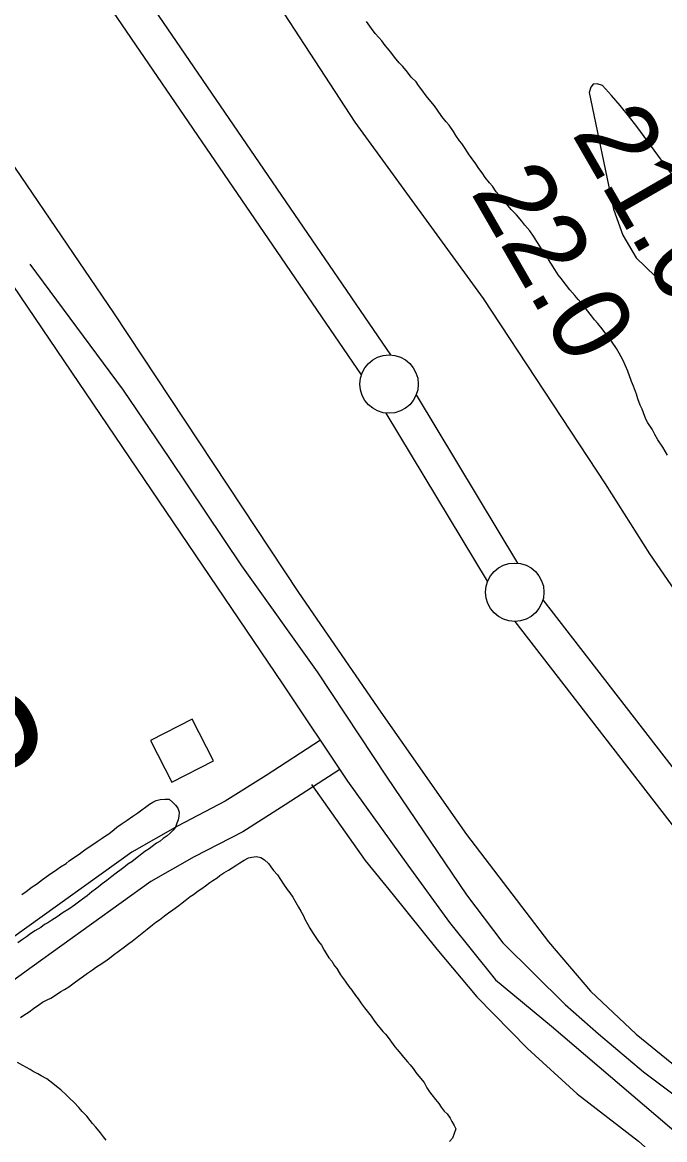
# Model space of a CAD drawing. Extents: x 3297753 to 3335611, y 652252 to 677623.
# Drawn here: x 3308297 to 3308846, y 669630 to 670586 of the extents above; entities that cross this region are included whole.
import ezdxf

# ---------------------------------------------------------------- set-up
doc = ezdxf.new("R2010")
doc.units = 0
for name, color, linetype in [('V-BLDG-OTLN', 7, 'Continuous'), ('V-LEVE-TOET', 7, 'Continuous'), ('V-RIVR-EDGE', 7, 'Continuous'), ('V-RIVR-RANG', 7, 'Continuous'), ('V-ROAD-CNTR', 7, 'Continuous'), ('V-SURV-IDEN', 7, 'Continuous'), ('V-SURV-LINE', 7, 'Continuous'), ('V-TOPO-MINR', 7, 'Continuous'), ('V-TOPO-SHOR', 7, 'Continuous')]:
    doc.layers.add(name, color=color, linetype=linetype)

msp = doc.modelspace()

# ---------------------------------------------------------------- linework, layer by layer
at = {"layer": 'V-BLDG-OTLN'}
msp.add_lwpolyline([(3308460.48, 669953.81), (3308442.28, 669989.42), (3308406.66, 669971.22), (3308424.87, 669935.6)], close=True, dxfattribs=at)
at = {"layer": 'V-LEVE-TOET'}
for points in [[(3308133.21, 670684.14), (3308250.51, 670519.66), (3308374.97, 670337.24), (3308533.16, 670097.88), (3308603.72, 669995.31), (3308676.85, 669890.86), (3308746.98, 669798.88), (3308783.09, 669756.81), (3308822.07, 669719.91), (3308908.96, 669649.25), (3309055.84, 669538.15), (3309202.86, 669430.58), (3309382.89, 669290.76), (3309531.09, 669190.18), (3309660.89, 669092.14), (3309690.67, 669067.09), (3309712.65, 669045.01), (3309817.76, 668967.41), (3309910.78, 668895.61), (3309933.41, 668877.39), (3310042.12, 668792.22), (3310236.32, 668633.29)], [(3308495.25, 670632.62), (3308581.29, 670500.31), (3308691.23, 670349.36), (3308795.55, 670190.72), (3308833.56, 670130.94), (3308923.2, 670000.24), (3308977.77, 669936.24), (3309079.06, 669851.75), (3309174.42, 669772.8), (3309318.58, 669660.06), (3309436.74, 669578.38), (3309522.36, 669519.23), (3309584.85, 669454.89), (3309681.74, 669370.59), (3309778.17, 669296), (3309850.52, 669235.65), (3309961.42, 669148.99), (3309983.33, 669131.68), (3310092.83, 669047.36), (3310290.15, 668899.76), (3310517.11, 668723.58)]]:
    msp.add_lwpolyline(points, dxfattribs=at)
at = {"layer": 'V-RIVR-EDGE'}
msp.add_spline([(3307850.62, 675821), (3307850.75, 675819.26), (3307852.36, 675798.53), (3307852.34, 675791.07), (3307856.9, 675791.47), (3307860.2, 675784), (3307858.08, 675766.6), (3307858.03, 675745.87), (3307859.68, 675743.8), (3307863.41, 675742.96), (3307863.4, 675739.64), (3307862.94, 675720.99), (3307866.19, 675694.04), (3307864.47, 675668.35), (3307864.85, 675653.43), (3307866.04, 675632.29), (3307865.98, 675608.25), (3307860.93, 675578), (3307855.03, 675536.15), (3307852.01, 675490.98), (3307848.61, 675457.42), (3307845.62, 675420.95), (3307843.09, 675401.89), (3307841.81, 675387.8), (3307842.17, 675364.59), (3307841.69, 675337.23), (3307844.13, 675320.65), (3307845.74, 675299.92), (3307848.96, 675263.02), (3307851.37, 675230.27), (3307851.72, 675204.99), (3307854.14, 675179.28), (3307856.98, 675153.99), (3307856.53, 675138.24), (3307855.69, 675135.76), (3307856.07, 675118.35), (3307855.63, 675111.72), (3307854.35, 675095.97), (3307852.65, 675077.74), (3307852.18, 675054.11), (3307855.44, 675031.72), (3307862.38, 674991.5), (3307864.8, 674962.48), (3307868.44, 674926), (3307870.05, 674906.1), (3307872.46, 674875.01), (3307874.08, 674859.25), (3307876.52, 674843.5), (3307878.94, 674816.13), (3307882.53, 674757.68), (3307886.15, 674712.5), (3307885.71, 674704.21), (3307884.45, 674697.99), (3307884.44, 674691.78), (3307887.31, 674680.16), (3307887.28, 674668.97), (3307887.26, 674658.2), (3307885.58, 674651.15), (3307881.01, 674644.12), (3307881, 674639.97), (3307886.35, 674626.28), (3307890.03, 674605.55), (3307895.77, 674578.59), (3307899.43, 674550.81), (3307909.27, 674510.58), (3307914.59, 674481.97), (3307918.25, 674453.78), (3307918.22, 674440.51), (3307919.86, 674433.88), (3307927.3, 674423.08), (3307927.28, 674417.7), (3307927.25, 674404.02), (3307928.48, 674400.28), (3307931.78, 674393.23), (3307935.06, 674376.64), (3307944.54, 674357.55), (3307954.85, 674337.22), (3307963.92, 674316.06), (3307975.42, 674271.68), (3307986.49, 674225.23), (3308000.06, 674178.77), (3308007.44, 674148.91), (3308015.22, 674108.27), (3308020.53, 674078.42), (3308024.25, 674072.19), (3308025.04, 674059.34), (3308025.41, 674039.44), (3308027.79, 673997.16), (3308030.63, 673971.46), (3308027.69, 673955.3), (3308027.24, 673943.28), (3308027.64, 673935.82), (3308029.69, 673925.45), (3308035.46, 673911.76), (3308035.42, 673899.32), (3308034.12, 673873.21), (3308036.13, 673851.24), (3308038.54, 673818.91), (3308040.98, 673799), (3308046.76, 673788.21), (3308050.46, 673778.26), (3308048.79, 673772.46), (3308048.76, 673761.27), (3308053.68, 673740.53), (3308060.66, 673711.09), (3308069.7, 673678.73), (3308069.66, 673665.06), (3308067.15, 673653.46), (3308067.55, 673650.14), (3308072.94, 673649.3), (3308077.91, 673648.87), (3308079.98, 673646.38), (3308086.52, 673608.64), (3308091.84, 673582.1), (3308104.58, 673536.48), (3308114.83, 673495), (3308121.38, 673461), (3308123.83, 673446.07), (3308127.95, 673436.12), (3308140.31, 673406.24), (3308148.95, 673377.21), (3308153.04, 673357.72), (3308158.34, 673321.23), (3308169, 673273.12), (3308189.1, 673188.1), (3308196.88, 673150.37), (3308207.96, 673103.92), (3308212.04, 673079.45), (3308214.06, 673059.97), (3308216.51, 673045.04), (3308218.98, 673035.91), (3308226, 673025.53), (3308228.46, 673015.99), (3308228.43, 673002.32), (3308230.49, 672996.92), (3308235.04, 672992.77), (3308235.02, 672984.48), (3308237.47, 672972.87), (3308241.99, 672953.37), (3308247.32, 672933.05), (3308253.9, 672910.65), (3308257.61, 672901.53), (3308263.8, 672890.32), (3308276.17, 672865), (3308277.39, 672856.3), (3308278.62, 672850.08), (3308283.16, 672844.26), (3308286.05, 672839.7), (3308286.04, 672832.24), (3308285.59, 672818.97), (3308288.47, 672812.33), (3308293.83, 672800.3), (3308303.72, 672777.89), (3308309.9, 672762.54), (3308316.07, 672743.05), (3308316.44, 672725.64), (3308318.1, 672723.15), (3308323.06, 672717.33), (3308327.59, 672706.13), (3308331.69, 672690.37), (3308330.84, 672679.6), (3308330.4, 672672.14), (3308332.46, 672667.16), (3308337.42, 672658.44), (3308343.59, 672642.67), (3308347.7, 672625.26), (3308355.91, 672595.39), (3308355.89, 672584.62), (3308357.53, 672579.64), (3308362.07, 672570.92), (3308366.61, 672563.45), (3308376.07, 672534), (3308399.56, 672478.4), (3308411.51, 672452.67), (3308418.52, 672435.25), (3308421.79, 672418.66), (3308423.01, 672409.95), (3308425.49, 672403.73), (3308428.79, 672397.5), (3308430.01, 672387.55), (3308434.95, 672375.52), (3308444.41, 672344.83), (3308450.58, 672326.99), (3308456.78, 672320.76), (3308459.66, 672312.87), (3308465.4, 672287.99), (3308467.43, 672268.09), (3308473.18, 672249.01), (3308476.05, 672236.57), (3308485.95, 672214.16), (3308490.05, 672198.81), (3308495.86, 672201.7), (3308496.67, 672193), (3308499.08, 672161.9), (3308505.23, 672134.53), (3308513.87, 672107.57), (3308522.52, 672084.75), (3308527.9, 672082.25), (3308536.2, 672087.2), (3308540.76, 672086.78), (3308539.51, 672083.88), (3308535.76, 672077.67), (3308534.91, 672067.73), (3308534.47, 672059.44), (3308531.96, 672050.74), (3308533.2, 672047.42), (3308536.91, 672037.88), (3308550.93, 672008.42), (3308564.93, 671974.39), (3308569.87, 671959.46), (3308576.49, 671954.88), (3308585.14, 671932.48), (3308595.86, 671910.49), (3308604.94, 671895.13), (3308605.76, 671888.49), (3308607.82, 671885.17), (3308610.71, 671881.02), (3308616.47, 671862.77), (3308627.6, 671838.7), (3308640.39, 671816.29), (3308660.99, 671765.26), (3308672.95, 671740.77), (3308685.32, 671715.46), (3308698.53, 671692.21), (3308700.17, 671685.58), (3308711.29, 671658.19), (3308728.21, 671627.9), (3308743.07, 671602.99), (3308758.34, 671575.6), (3308771.97, 671554.84), (3308775.27, 671548.61), (3308783.11, 671536.16), (3308790.54, 671522.88), (3308793.43, 671519.55), (3308797.16, 671517.06), (3308801.29, 671511.24), (3308803.76, 671502.95), (3308810.8, 671502.1), (3308815.77, 671499.19), (3308833.53, 671474.28), (3308845.09, 671458.5), (3308857.08, 671443.55), (3308870.72, 671429.01), (3308882.71, 671418.61), (3308908.77, 671397), (3308930.27, 671375.39), (3308944.33, 671361.26), (3308952.58, 671346.74), (3308960.43, 671336.77), (3308966.22, 671331.78), (3308972.85, 671328.86), (3308985.64, 671307.28), (3309001.75, 671282.37), (3309010.84, 671271.57), (3309010.83, 671268.25), (3309008.34, 671266.19), (3309011.64, 671262.03), (3309018.66, 671250.83), (3309024.85, 671237.13), (3309035.15, 671212.24), (3309059.5, 671169.07), (3309066.5, 671150.82), (3309067.71, 671140.45), (3309071.85, 671135.88), (3309077.22, 671128.41), (3309078.45, 671123.02), (3309078.43, 671117.63), (3309082.15, 671111.4), (3309089.15, 671092.73), (3309098.63, 671073.23), (3309111.41, 671045.01), (3309116.36, 671032.15), (3309123.35, 671011), (3309128.7, 670995.65), (3309133.23, 670984.86), (3309143.97, 670967.42), (3309159.66, 670945.42), (3309169.17, 670933.37), (3309181.99, 670924.22), (3309188.19, 670917.16), (3309197.69, 670902.22), (3309217.1, 670874.81), (3309231.57, 670859.03), (3309239.82, 670845.33), (3309244.79, 670840.76), (3309252.23, 670835.35), (3309260.51, 670831.18), (3309275.4, 670817.06), (3309282.43, 670810.41), (3309290.69, 670800.02), (3309303.1, 670788.39), (3309315.92, 670775.51), (3309335.34, 670751), (3309344.42, 670736.47), (3309351.03, 670726.51), (3309360.13, 670721.51), (3309375.84, 670704.9), (3309390.72, 670688.69), (3309403.11, 670668.77), (3309415.49, 670646.77), (3309426.65, 670635.14), (3309442.78, 670618.52), (3309454.34, 670603.15), (3309462.18, 670588.63), (3309470.85, 670575.34), (3309476.63, 670563.31), (3309487.39, 670558.31), (3309488.62, 670554.57), (3309489.44, 670550.84), (3309494.82, 670544.2), (3309506.81, 670533.39), (3309523.77, 670518.84), (3309529.95, 670505.98), (3309538.6, 670484.82), (3309549.72, 670453.7), (3309551.35, 670440.85), (3309555.47, 670430.89), (3309568.67, 670408.89), (3309577.35, 670396.02), (3309581.47, 670386.48), (3309581.46, 670383.16), (3309578.55, 670379.85), (3309576.88, 670374.88), (3309582.24, 670364.09), (3309594.61, 670336.71), (3309604.49, 670308.91), (3309606.94, 670296.06), (3309614.38, 670284.85), (3309627.18, 670266.99), (3309635.46, 670261.59), (3309639.18, 670259.92), (3309638.74, 670249.97), (3309639.54, 670236.29), (3309641.18, 670228), (3309644.89, 670221.36), (3309656.46, 670208.06), (3309664.31, 670195.61), (3309663.46, 670188.15), (3309663.84, 670176.13), (3309667.96, 670166.17), (3309673.34, 670159.94), (3309684.07, 670142.92), (3309690.66, 670126.33), (3309700.14, 670102.68), (3309716.65, 670076.52)], degree=3, dxfattribs=at)
at = {"layer": 'V-ROAD-CNTR'}
for points in [[(3307339.14, 672310.87), (3307407.41, 672029.86), (3307476.95, 671732.57), (3307511.07, 671600.1), (3307529.82, 671540.23), (3307554.17, 671481.54), (3307565.65, 671454.66), (3307628.51, 671339.43), (3307687.48, 671244.51), (3307819.52, 671049.73), (3308010.54, 670769.93), (3308276.08, 670379.16), (3308519.64, 670019.78), (3308575.25, 669936.41), (3308626.7, 669864.47), (3308662.44, 669815.55), (3308701.66, 669766.43), (3308749.57, 669726.83), (3308879.73, 669615.8), (3309312.15, 669283.51), (3309781.29, 668929.63), (3310172.08, 668625.19)], [(3308552.14, 669971.42), (3308505.63, 669941.31), (3308470.59, 669919.23), (3308429.58, 669897.99), (3308390.61, 669875.75), (3308287.73, 669801.85), (3307991.97, 669587.42), (3307744.65, 669410.84)], [(3308568.45, 669946.24), (3308521.78, 669916.02), (3308485.5, 669893.17), (3308443.92, 669871.63), (3308406.84, 669850.47), (3308305.29, 669777.52), (3308009.49, 669563.07), (3307762.08, 669386.42)]]:
    msp.add_lwpolyline(points, dxfattribs=at)
at = {"layer": 'V-SURV-LINE'}
for points in [[(3307777.67, 671521.09), (3308611.79, 670301.17)], [(3308587.02, 670284.24), (3307752.9, 671504.17)], [(3308633.84, 670266.87), (3308720.71, 670122.95)], [(3308695.03, 670107.44), (3308608.16, 670251.36)], [(3308742.29, 670091.46), (3308891.58, 669898.46)], [(3308867.84, 669880.11), (3308718.55, 670073.11)]]:
    msp.add_lwpolyline(points, dxfattribs=at)
for centre in [(3308610.68, 670276.22), (3308718.19, 670098.09)]:
    msp.add_circle(centre, 25, dxfattribs=at)
at = {"layer": 'V-TOPO-MINR'}
msp.add_lwpolyline([(3308864.08, 670440.19), (3308822.53, 670496.68), (3308815.59, 670505.74), (3308808.42, 670514.61), (3308800.91, 670523.2), (3308793.18, 670531.6), (3308788.84, 670533.08), (3308785.39, 670532.87), (3308783.26, 670530.14), (3308782.01, 670525.73), (3308802.7, 670425.91), (3308810.75, 670403.77), (3308822.11, 670384.24), (3308838.44, 670368.63), (3308858.08, 670355.63)], dxfattribs=at)
at = {"layer": 'V-TOPO-SHOR'}
for points in [[(3308783.89, 670334.51), (3308779.72, 670339.98), (3308777.21, 670343.17), (3308772.6, 670348.65), (3308769.65, 670351.86), (3308765.45, 670356.89), (3308762.52, 670360.54), (3308757.93, 670366.46), (3308755.42, 670369.65), (3308752.52, 670374.18), (3308749.23, 670379.61), (3308747.16, 670382.78), (3308744.71, 670387.29), (3308741.36, 670391.4), (3308739.71, 670394.11), (3308737.24, 670398.18), (3308734.35, 670402.71), (3308731.01, 670407.26), (3308726.82, 670412.28), (3308724.31, 670415.47), (3308719.7, 670420.96), (3308715.05, 670425.56), (3308712.54, 670428.75), (3308708.77, 670433.32), (3308704.99, 670437.88), (3308702.46, 670440.64), (3308699.15, 670445.62), (3308696.62, 670448.37), (3308692.85, 670452.94), (3308690.78, 670456.11), (3308687.05, 670461.56), (3308684.98, 670464.73), (3308680.8, 670470.19), (3308678.73, 670473.37), (3308676.25, 670477), (3308672.93, 670481.98), (3308670.82, 670484.28), (3308667.93, 670488.81), (3308665.88, 670492.42), (3308662.15, 670497.86), (3308659.62, 670500.61), (3308655.85, 670505.18), (3308652.11, 670510.63), (3308649.62, 670514.26), (3308645.01, 670519.74), (3308642.5, 670522.93), (3308638.75, 670527.94), (3308635.81, 670531.59), (3308633.75, 670534.76), (3308629.52, 670538.91), (3308626.6, 670542.99), (3308622.41, 670548.02), (3308619.46, 670551.23), (3308615.25, 670555.81), (3308613.18, 670558.98), (3308609.41, 670563.55), (3308607.3, 670565.84), (3308604.39, 670569.93), (3308601.86, 670572.68), (3308598.94, 670576.33), (3308595.58, 670580.44), (3308591.43, 670586.34)], [(3308303.43, 670378.82), (3308383.14, 670270.91), (3308422.75, 670212.46), (3308484.45, 670120.77), (3308549.12, 670029.93), (3308608.92, 669939.79), (3308677.08, 669839.02), (3308708.14, 669798.07), (3308761.21, 669745.41), (3308790, 669720.2), (3308828.27, 669687.75), (3308884.24, 669645.73), (3308960.13, 669588.68), (3309035.43, 669529.21), (3309126.09, 669462.72), (3309221.26, 669387.24), (3309313.59, 669313.83), (3309396.07, 669250.62), (3309483.65, 669180.84), (3309563.45, 669123.63), (3309622.17, 669077.09), (3309654.59, 669045.37)], [(3308848.91, 670215.43), (3308844.79, 670222.21), (3308840.65, 670228.56), (3308838.2, 670233.07), (3308835.75, 670237.58), (3308832.01, 670243.03), (3308830.38, 670246.18), (3308828.41, 670251.55), (3308827.22, 670254.69), (3308825.61, 670258.28), (3308823.63, 670263.65), (3308822.48, 670267.67), (3308819.68, 670274.39), (3308818.09, 670278.43), (3308814.94, 670287.37), (3308810.92, 670296.36), (3308807.66, 670302.66), (3308805.19, 670306.73), (3308801.45, 670312.18), (3308798.96, 670315.81), (3308795.19, 670320.38), (3308793.12, 670323.55), (3308789.35, 670328.11), (3308786.4, 670331.32), (3308783.89, 670334.51)], [(3308544.23, 669933.42), (3308590.17, 669868.64), (3308614.17, 669839.09), (3308651.48, 669792.63), (3308685.75, 669751.9), (3308729.23, 669707.5), (3308771.54, 669668.77), (3308824.07, 669628.2), (3308882.65, 669576.15), (3308936.45, 669532.73), (3308997.76, 669489.92), (3309061.11, 669440.01), (3309147.21, 669375.1), (3309187.52, 669344.41), (3309284.28, 669266.43), (3309360.01, 669210.84), (3309424.24, 669159.49), (3309496.67, 669103.12), (3309550.55, 669061.56), (3309616.94, 669007.49)], [(3308402.3, 669914.14), (3308405.63, 669916.64), (3308408.64, 669918.56), (3308411.34, 669919.91), (3308414.88, 669920.64), (3308419, 669921.05), (3308422.51, 669920.9), (3308425.34, 669918.44), (3308427.87, 669915.99), (3308430.1, 669913.26), (3308431.13, 669909.99), (3308430.98, 669906.48), (3308430.26, 669903.29), (3308429.26, 669900.4), (3308427.94, 669896.94), (3308426.08, 669894.39), (3308423.33, 669891.86), (3308420.89, 669889.62), (3308417.58, 669887.42), (3308414.85, 669885.19), (3308411.83, 669883.27), (3308407.91, 669880.51), (3308405.48, 669878.56), (3308401.86, 669876.07), (3308399.14, 669874.14), (3308396.41, 669871.91), (3308393.69, 669869.97), (3308390.66, 669867.47), (3308387.34, 669865.26), (3308384.91, 669863.32), (3308381.58, 669860.82), (3308377.35, 669857.78), (3308373.42, 669854.72), (3308369.17, 669851.38), (3308365.25, 669848.62), (3308361.91, 669845.83), (3308359.48, 669843.88), (3308356.46, 669841.67), (3308352.5, 669838.32), (3308348.58, 669835.56), (3308346.15, 669833.61), (3308341.62, 669830.28), (3308336.79, 669826.97), (3308331.97, 669823.95), (3308326.84, 669820.36), (3308322.32, 669817.33), (3308318.71, 669815.14), (3308316.01, 669813.79), (3308312.69, 669811.29), (3308307.58, 669808.29), (3308303.05, 669805.26), (3308300.63, 669803.31), (3308297.01, 669800.82), (3308293.08, 669798.06)], [(3308296.59, 669839.52), (3308300.21, 669842), (3308305.36, 669845.88), (3308308.98, 669848.37), (3308314.13, 669852.25), (3308319.26, 669855.84), (3308326.5, 669860.81), (3308329.53, 669863.02), (3308334.34, 669866.04), (3308337.07, 669868.27), (3308341.6, 669871.3), (3308345.52, 669874.06), (3308348.24, 669876), (3308351.57, 669878.5), (3308358.2, 669882.9), (3308360.92, 669884.84), (3308365.14, 669887.59), (3308368.15, 669889.52), (3308370.87, 669891.45), (3308375.42, 669895.07), (3308377.85, 669897.01), (3308381.47, 669899.5), (3308386.6, 669903.09), (3308391.43, 669906.4), (3308395.66, 669909.44), (3308399.28, 669911.93), (3308402.3, 669914.14)], [(3308295.31, 669734.07), (3308298.17, 669736.26), (3308302.69, 669739.08), (3308306.5, 669741.92), (3308311.02, 669744.96), (3308314.12, 669747.14), (3308318.14, 669749.28), (3308321.21, 669750.77), (3308326.19, 669753.79), (3308330, 669756.41), (3308333.07, 669758.12), (3308336.87, 669760.51), (3308341.4, 669763.78), (3308345.47, 669767.07), (3308348.55, 669769.02), (3308352.85, 669772.08), (3308356.89, 669774.91), (3308359.52, 669776.88), (3308362.62, 669779.06), (3308367.6, 669782.08), (3308371.41, 669784.92), (3308374.76, 669787.56), (3308380.01, 669791.49), (3308383.12, 669793.9), (3308388.12, 669797.39), (3308390.99, 669799.58), (3308393.85, 669801.77), (3308398.16, 669805.28), (3308401.03, 669807.47), (3308403.9, 669809.89), (3308408.21, 669813.41), (3308411.08, 669815.6), (3308414.4, 669817.77), (3308418.7, 669821.05), (3308422.05, 669823.68), (3308425.86, 669826.3), (3308430.87, 669830.01), (3308433.73, 669832.2), (3308436.37, 669834.4), (3308440.67, 669837.68), (3308443.29, 669839.42), (3308447.34, 669842.49), (3308450.44, 669844.67), (3308453.54, 669846.84), (3308457.35, 669849.69), (3308459.97, 669851.43), (3308463.53, 669853.59), (3308465.92, 669855.57), (3308469.26, 669857.96), (3308473.28, 669860.1), (3308476.38, 669862.29), (3308480.42, 669864.89), (3308483.03, 669866.63), (3308486.82, 669868.78), (3308490.37, 669870.71), (3308493.41, 669871.5), (3308497.35, 669871.8), (3308501.02, 669871.18), (3308504.17, 669869.2), (3308507.5, 669866.05), (3308509.69, 669863.19), (3308511.87, 669860.09), (3308515.18, 669856.25), (3308517.78, 669852.21), (3308519.96, 669849.12), (3308523.43, 669843.65), (3308525.84, 669840.78), (3308528.24, 669837.21), (3308531.05, 669832.7), (3308533.19, 669828.68), (3308535.35, 669825.12), (3308537.49, 669821.1), (3308538.76, 669818.28), (3308541.11, 669813.79)], [(3308541.11, 669813.79), (3308542.83, 669810.71), (3308545.21, 669806.91), (3308547.6, 669803.34), (3308550.42, 669799.06), (3308552.84, 669796.19), (3308555.19, 669791.7), (3308556.92, 669788.85), (3308559.31, 669785.28), (3308561.73, 669782.41), (3308564.1, 669778.38), (3308566.08, 669775.98), (3308569.1, 669770.77), (3308571.72, 669767.19), (3308573.68, 669764.34), (3308576.3, 669760.76), (3308578.93, 669757.41), (3308581.98, 669753.12), (3308584.4, 669750.02), (3308587, 669745.98), (3308589.62, 669742.4), (3308593.14, 669738.09), (3308595.32, 669735.23), (3308597.72, 669731.89), (3308599.9, 669728.79), (3308602.77, 669725.44), (3308605.41, 669722.32), (3308607.62, 669719.92), (3308610.04, 669717.04), (3308612.87, 669712.99), (3308615.71, 669709.17), (3308617.69, 669706.78), (3308620.76, 669702.95), (3308623.19, 669700.3), (3308626.49, 669696.24), (3308628.69, 669693.6), (3308631.33, 669690.49), (3308633.73, 669687.15), (3308637.46, 669682.37), (3308640.76, 669678.53), (3308643.11, 669674.04), (3308645.27, 669670.48), (3308647.25, 669668.09), (3308650.54, 669664.02), (3308653.4, 669660.43), (3308655.35, 669657.34), (3308657.75, 669654.01), (3308660.42, 669651.58), (3308663.04, 669648.01), (3308664.53, 669645.17), (3308666.48, 669641.85), (3308667.96, 669638.78), (3308665.08, 669630.82)], [(3308337.46, 669665.27), (3308334.79, 669667.69), (3308329.9, 669672.29), (3308326.32, 669675.21), (3308322.96, 669677.67), (3308320.5, 669679.62), (3308317.81, 669681.58), (3308313.08, 669684.33), (3308310.37, 669685.83), (3308306.3, 669688.08), (3308303.59, 669689.58), (3308297.5, 669693.08), (3308292.75, 669695.58)], [(3308368.75, 669629.28), (3308366.33, 669632.15), (3308363.7, 669635.5), (3308359.74, 669640.29), (3308357.1, 669643.4), (3308354.9, 669646.04), (3308352.05, 669649.63), (3308348.29, 669653.71), (3308345.2, 669657.08), (3308341.22, 669661.41), (3308337.46, 669665.27)], [(3308665.08, 669630.82), (3308662.42, 669627.93)]]:
    msp.add_lwpolyline(points, dxfattribs=at)

# ---------------------------------------------------------------- texts
at = {"layer": 'V-RIVR-RANG'}
for s, p in [('21.0', (3308766.38, 670490.66)), ('22.0', (3308679.86, 670440.52))]:
    msp.add_text(s, height=67, rotation=299.94833, dxfattribs=at).set_placement(p)
at = {"layer": 'V-SURV-IDEN'}
msp.add_text('4239+73.6', height=100, rotation=28.1246, dxfattribs=at).set_placement((3307764.44, 669668.13))

doc.saveas('drawing.dxf')
